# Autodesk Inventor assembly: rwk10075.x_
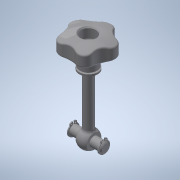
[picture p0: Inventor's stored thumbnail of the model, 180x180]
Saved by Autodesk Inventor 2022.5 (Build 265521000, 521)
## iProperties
Part Number: rwk10075.x_
Material: 一般
Document SubType Name: Assembly
Designer: ImaoCorp
Sending System: SOLIDWORKS 2017-2017317
MC: AMD64
MC_MODEL: Intel64 Family 6 Model 60 Stepping 3, GenuineIntel
OS: Windows_NT
FRU: Parasolid Version 29.0, build 201,  4-17-2017
FORMAT: text
GUISE: transmit
KEY: rwk10075
FILE: rwk10075.x_t
DATE: Wed Sep 04 15:56:36 2019
Author: ImaoCorp
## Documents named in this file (3)
- X:\14_SW2022-Inv2022\00_全2023-1023新製品(TCC)まで\r\rwk10075\RWK10075.iam
- X:\14_SW2022-Inv2022\00_全2023-1023新製品(TCC)まで\r\rwk10075\rwk10075_01.ipt
- X:\14_SW2022-Inv2022\00_全2023-1023新製品(TCC)まで\r\rwk10075\rwk10075_02.ipt
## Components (2 placed, 2 different names)
1. rwk10075_01
2. rwk10075_02
